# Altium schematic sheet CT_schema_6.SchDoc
size 278 x 170 mm
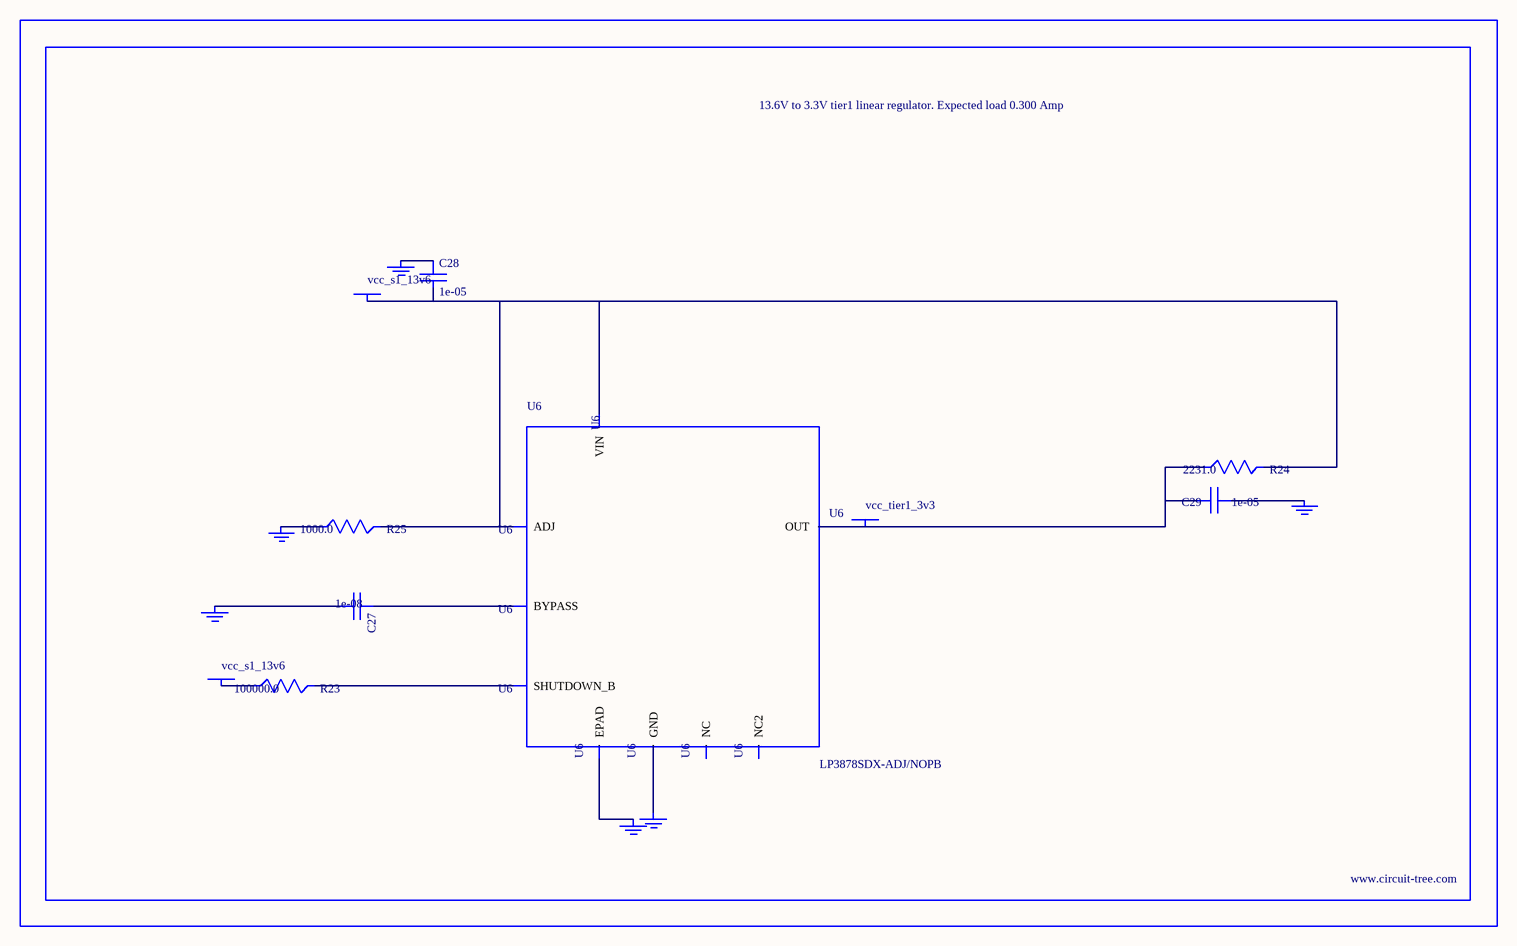
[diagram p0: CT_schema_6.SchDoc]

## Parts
BORDER5  (no value)
C27  1e-08  [C0402]
C28  1e-05  [C1210]
C29  1e-05  [C1210]
GND_INSTANCE_5_0  (no value)
GND_INSTANCE_5_1  (no value)
GND_INSTANCE_5_2  (no value)
GND_INSTANCE_5_3  (no value)
GND_INSTANCE_5_4  (no value)
GND_INSTANCE_5_5  (no value)
POWER_INSTANCE_5_0  vcc_s1_13v6
POWER_INSTANCE_5_1  vcc_s1_13v6
POWER_INSTANCE_5_2  vcc_tier1_3v3
R23  100000.0  [R0603]
R24  2231.0  [R0603]
R25  1000.0  [R0603]
U6  LP3878SDX-ADJ/NOPB  [WSON-8]

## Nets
NetC27_1: C27.1 U6.1(BYPASS)
NetC27_2: C27.2 GND_INSTANCE_5_0.0(GND)
NetC28_1: C28.1 GND_INSTANCE_5_1.0(GND)
NetC28_2: C28.2 POWER_INSTANCE_5_0.0(PWR) R24.2 R25.2 U6.4(VIN) U6.6(ADJ)
NetC29_1: C29.1 GND_INSTANCE_5_2.0(GND)
NetC29_2: C29.2 POWER_INSTANCE_5_2.0(PWR) R24.1 U6.5(OUT)
NetGND_INSTANCE_5_3_0: GND_INSTANCE_5_3.0(GND) R25.1
NetGND_INSTANCE_5_4_0: GND_INSTANCE_5_4.0(GND) U6.PAD(EPAD)
NetGND_INSTANCE_5_5_0: GND_INSTANCE_5_5.0(GND) U6.3(GND)
NetPOWER_INSTANCE_5_1_0: POWER_INSTANCE_5_1.0(PWR) R23.1
NetR23_2: R23.2 U6.8(SHUTDOWN_B)

Not connected (* = marked no-connect by the designer): U6 2(NC) 7(NC2)

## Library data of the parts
BORDER5 = BORDER_PAGE5
C27 = C0402C103K3RAC
C28 = C1210C106K5PACTU
C29 = GRM32DR61E106MA12L
GND_INSTANCE_5_0-GND_INSTANCE_5_5 = GND
POWER_INSTANCE_5_0-POWER_INSTANCE_5_2 = PWR
R23 = RC0603JR-07100KL
R24 = R24
R25 = RC0603JR-071KL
